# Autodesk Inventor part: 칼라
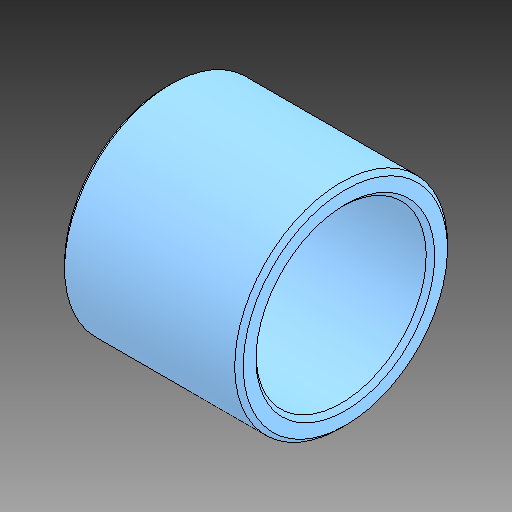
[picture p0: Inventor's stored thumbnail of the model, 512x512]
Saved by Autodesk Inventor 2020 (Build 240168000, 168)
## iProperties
Created: 2024-08
Part Number: 칼라
Material: 강철, 연강
Document SubType Name: Modeling
Designer: 1강의실14
Density: 7.85 g/cm^3
Appearance: 기본값
Author: jhkim
Sending System: Autodesk Inventor 2025
Preprocessor: ST-DEVELOPER v20
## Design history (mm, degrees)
feature "솔리드1"
node "솔리드2"
